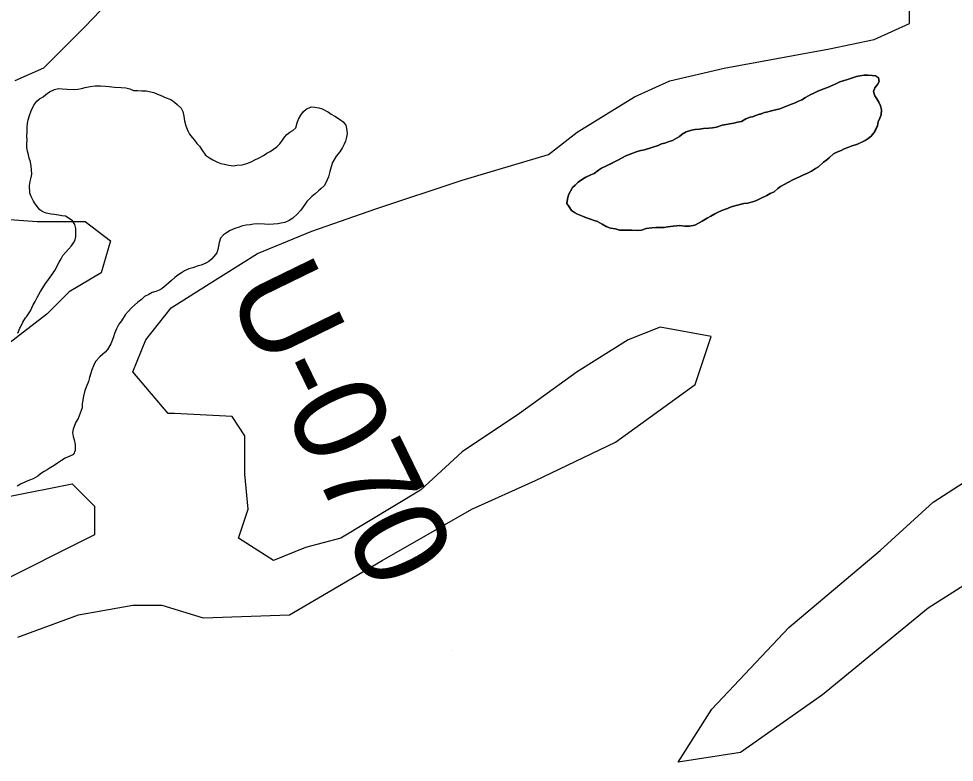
# Model space of a CAD drawing. Extents: x 3177385 to 3215275, y 903885 to 929304.
# Drawn here: x 3187679 to 3188514, y 913275 to 913939 of the extents above; entities that cross this region are included whole.
import ezdxf

# ---------------------------------------------------------------- set-up
doc = ezdxf.new("R2010")
doc.units = 0
for name, color, linetype in [('V-RIVR-RANG', 7, 'Continuous'), ('V-RIVR-RANG-IDEN', 7, 'Continuous'), ('V-SITE-VEGE', 7, 'Continuous'), ('V-TOPO-SHOR', 7, 'Continuous')]:
    doc.layers.add(name, color=color, linetype=linetype)

msp = doc.modelspace()

# ---------------------------------------------------------------- linework, layer by layer
at = {"layer": 'V-RIVR-RANG'}
msp.add_line((3188065.58, 913375.16), (3188065.58, 913375.16), dxfattribs=at)
at = {"layer": 'V-SITE-VEGE'}
for points in [[(3187852.4, 914017.74), (3187792.5, 913989.19), (3187738.3, 913932.1), (3187701.21, 913895), (3187675.54, 913883.58)], [(3187678.39, 913386.92), (3187732.59, 913406.9), (3187781.09, 913415.47), (3187806.76, 913415.47), (3187843.85, 913404.05), (3187920.87, 913406.9), (3188003.59, 913455.43), (3188083.47, 913501.1), (3188140.52, 913526.79), (3188211.84, 913561.04), (3188283.15, 913612.42), (3188297.42, 913655.23), (3188251.77, 913663.8), (3188223.25, 913652.38), (3188177.61, 913623.84), (3188126.26, 913586.73), (3188074.91, 913552.47), (3188037.83, 913518.22), (3187966.51, 913475.41), (3187935.13, 913466.85), (3187906.6, 913455.43), (3187875.23, 913475.41), (3187883.78, 913501.1), (3187880.93, 913532.49), (3187880.93, 913566.75), (3187869.52, 913583.87), (3187818.17, 913586.73), (3187812.47, 913586.73), (3187781.09, 913623.84), (3187792.5, 913652.38), (3187815.32, 913680.92), (3187846.7, 913700.9), (3187892.34, 913729.44), (3187940.84, 913749.42), (3187997.89, 913769.41), (3188074.91, 913795.1), (3188151.93, 913817.93), (3188177.61, 913837.91), (3188228.95, 913869.31), (3188260.33, 913883.58), (3188308.83, 913895), (3188402.97, 913912.12), (3188442.9, 913920.69), (3188474.28, 913934.96), (3188474.28, 913946.38)], [(3188443.32, 913870.14), (3188442.34, 913874.21), (3188443.47, 913877.39), (3188445.67, 913880.32), (3188447.22, 913883.07), (3188446.65, 913886.28), (3188444.13, 913888.04), (3188441.15, 913888.53), (3188437.32, 913888.82), (3188433.91, 913888.68), (3188430.05, 913888.12), (3188427.05, 913887.55), (3188422.55, 913886.15), (3188419.11, 913884.94), (3188415.03, 913883.75), (3188412.03, 913882.75), (3188408.58, 913881.12), (3188405.78, 913879.89), (3188401.04, 913877.86), (3188396.96, 913876.25), (3188391.79, 913874.01), (3188388.99, 913872.79), (3188385.76, 913871.15), (3188381.45, 913868.9), (3188378.21, 913866.83), (3188375.4, 913865.4), (3188372.39, 913863.97), (3188368.95, 913862.77), (3188365.94, 913861.55), (3188361.64, 913859.94), (3188358.63, 913858.72), (3188354.77, 913857.74), (3188351.12, 913856.96), (3188346.84, 913855.78), (3188344.91, 913855.39), (3188343.4, 913854.78), (3188341.47, 913853.97), (3188340.4, 913853.78), (3188336.31, 913852.37), (3188334.16, 913851.56), (3188332.02, 913851.18), (3188328.37, 913849.77), (3188324.26, 913847.3), (3188320.84, 913846.73), (3188317.41, 913845.95), (3188313.99, 913845.38), (3188310.78, 913844.81), (3188307.13, 913844.04), (3188301.98, 913842.44), (3188298.34, 913841.66), (3188295.13, 913841.31), (3188290.43, 913840.98), (3188287.01, 913840.41), (3188282.96, 913840.29), (3188279.74, 913839.5), (3188275.02, 913838.11), (3188271.35, 913836.06), (3188268.96, 913833.98), (3188262.92, 913830.48), (3188259.05, 913829.28), (3188256.04, 913828.07), (3188253.04, 913827.49), (3188250.03, 913826.06), (3188237.78, 913822.06), (3188234.57, 913821.49)], [(3188234.57, 913821.49), (3188231.14, 913820.49), (3188224.9, 913818.07), (3188221.25, 913816.65), (3188217.37, 913814.6), (3188214.56, 913813.17), (3188211.55, 913811.74), (3188203.78, 913807.64), (3188199.27, 913805.82), (3188196.67, 913803.95), (3188192.98, 913801.04), (3188189.97, 913799.83), (3188185.45, 913797.79), (3188182.42, 913795.94), (3188178.52, 913793.04), (3188175.91, 913790.53), (3188173.52, 913788.45), (3188171.74, 913785.08), (3188169.96, 913781.92), (3188169.03, 913778.1), (3188168.52, 913774.06), (3188170.37, 913771.03), (3188172.66, 913768), (3188175.18, 913766.24), (3188177.92, 913764.69), (3188182.36, 913762.89), (3188185.95, 913761.32), (3188189.55, 913760.17), (3188192.94, 913759.04), (3188195.9, 913758.12), (3188200.12, 913755.68), (3188203.7, 913753.47), (3188207.29, 913752.12), (3188211.75, 913751.38), (3188215.36, 913750.46), (3188218.56, 913750.39), (3188231.77, 913750.1), (3188235.19, 913750.46), (3188239.28, 913751.86), (3188244.19, 913752.4), (3188248.04, 913752.74), (3188251.87, 913752.66), (3188255.29, 913752.8), (3188258.71, 913753.16), (3188263.42, 913753.91), (3188269.18, 913754.43), (3188273.65, 913753.9), (3188277.92, 913754.02), (3188282.84, 913754.77), (3188286.51, 913756.83), (3188289.31, 913758.26), (3188293.85, 913760.94), (3188297.09, 913762.79), (3188300.54, 913764.85), (3188304.21, 913766.69), (3188308.3, 913768.52), (3188311.95, 913769.72), (3188315.18, 913771.15), (3188318.4, 913772.15), (3188326.33, 913774.11), (3188330.18, 913774.45), (3188336.4, 913776.24), (3188339.63, 913777.66), (3188342.65, 913779.31), (3188346.96, 913781.35), (3188349.98, 913782.99), (3188353.42, 913784.62), (3188356.9, 913787.53), (3188359.28, 913789.4), (3188362.95, 913791.45), (3188365.76, 913792.89), (3188371.37, 913795.97), (3188376.1, 913798), (3188379.12, 913799.43), (3188383.42, 913801.25), (3188386.87, 913802.89), (3188390.54, 913805.37), (3188393.14, 913807.02), (3188397.49, 913810.98), (3188400.52, 913813.26), (3188402.91, 913815.34), (3188406.39, 913818.47), (3188409.41, 913819.89), (3188413.28, 913821.52), (3188416.08, 913822.95), (3188419.31, 913824.16), (3188422.32, 913825.38), (3188427.9, 913827.18), (3188434.8, 913830.44), (3188437.39, 913832.31), (3188440, 913834.38), (3188442.62, 913837.31), (3188445.95, 913843.64), (3188446.45, 913847.04), (3188447.8, 913850.21), (3188448.93, 913853.17), (3188449.24, 913857.65), (3188448.46, 913861.29), (3188447.04, 913864.52), (3188445.19, 913867.75), (3188443.32, 913870.14)], [(3187658.43, 913760.84), (3187695.51, 913757.99), (3187738.3, 913757.99), (3187761.12, 913740.86), (3187752.56, 913712.32), (3187724.04, 913695.19), (3187704.07, 913675.21), (3187655.57, 913638.11)], [(3188585.72, 913472.92), (3188491.18, 913412.73), (3188396.64, 913335.34), (3188323.59, 913283.74), (3188267.72, 913275.14), (3188297.8, 913322.44), (3188366.56, 913395.53), (3188448.21, 913464.32), (3188495.48, 913507.31), (3188568.53, 913554.61)], [(3187669.84, 913512.51), (3187726.89, 913523.93), (3187746.86, 913503.95), (3187746.86, 913478.26), (3187655.57, 913432.59)]]:
    msp.add_lwpolyline(points, dxfattribs=at)
at = {"layer": 'V-TOPO-SHOR'}
for points in [[(3188250.03, 913826.06), (3188253.04, 913827.49), (3188256.04, 913828.07), (3188259.05, 913829.28), (3188262.92, 913830.48), (3188268.96, 913833.97), (3188271.35, 913836.06), (3188275.02, 913838.11), (3188279.74, 913839.5), (3188282.96, 913840.29), (3188287.01, 913840.41), (3188290.43, 913840.98), (3188295.13, 913841.31), (3188298.34, 913841.66), (3188301.98, 913842.44), (3188307.13, 913844.04), (3188310.78, 913844.81), (3188313.99, 913845.38), (3188317.41, 913845.95), (3188320.84, 913846.73), (3188324.26, 913847.3), (3188328.37, 913849.77), (3188332.02, 913851.18), (3188334.16, 913851.56), (3188336.31, 913852.37), (3188340.4, 913853.78), (3188341.46, 913853.97), (3188343.4, 913854.78), (3188344.91, 913855.39), (3188346.84, 913855.77), (3188351.12, 913856.96), (3188354.77, 913857.74), (3188358.63, 913858.72), (3188361.64, 913859.94), (3188365.94, 913861.55), (3188368.95, 913862.77), (3188372.39, 913863.97), (3188375.4, 913865.4), (3188378.21, 913866.83), (3188381.45, 913868.9), (3188385.76, 913871.15), (3188388.99, 913872.79), (3188391.79, 913874.01), (3188396.96, 913876.25), (3188401.04, 913877.86), (3188405.78, 913879.89), (3188408.58, 913881.12), (3188412.03, 913882.75), (3188415.03, 913883.75), (3188419.11, 913884.94), (3188422.55, 913886.15), (3188427.05, 913887.55), (3188430.05, 913888.12), (3188433.91, 913888.68), (3188437.32, 913888.82), (3188441.15, 913888.53), (3188444.13, 913888.04), (3188444.76, 913887.6), (3188446.65, 913886.28), (3188447.22, 913883.07), (3188445.67, 913880.32), (3188443.47, 913877.39), (3188442.34, 913874.21), (3188443.32, 913870.14), (3188445.19, 913867.75), (3188447.04, 913864.52), (3188448.46, 913861.29), (3188449.24, 913857.65), (3188448.93, 913853.17), (3188447.8, 913850.21), (3188446.45, 913847.04), (3188445.95, 913843.64), (3188444.18, 913840.27), (3188442.62, 913837.31), (3188440, 913834.38), (3188437.39, 913832.31), (3188434.8, 913830.44), (3188431.78, 913829.01), (3188427.9, 913827.18), (3188422.32, 913825.38), (3188419.31, 913824.16), (3188416.08, 913822.95), (3188413.28, 913821.52), (3188409.41, 913819.89), (3188406.39, 913818.47), (3188402.91, 913815.34), (3188400.52, 913813.26), (3188397.49, 913810.98), (3188393.14, 913807.02), (3188390.54, 913805.37), (3188386.87, 913802.89), (3188383.42, 913801.25), (3188379.12, 913799.43), (3188376.1, 913798), (3188371.37, 913795.97), (3188365.76, 913792.89), (3188362.95, 913791.45), (3188359.28, 913789.4), (3188356.9, 913787.53), (3188353.42, 913784.62), (3188349.98, 913782.99)], [(3187693.21, 913774.8), (3187692.37, 913776.09), (3187690.11, 913780.41), (3187688.9, 913783.42), (3187688.83, 913790.24), (3187689.33, 913793.86), (3187690.05, 913797.47), (3187690.75, 913800.44), (3187690.62, 913804.28), (3187690.26, 913807.49), (3187689.49, 913811.34), (3187688.49, 913814.56), (3187687.71, 913817.56), (3187686.93, 913820.99), (3187686.35, 913824.2), (3187686.21, 913827.41), (3187686.49, 913830.81), (3187686.35, 913834.01), (3187686.66, 913838.49), (3187686.74, 913842.32), (3187686.81, 913845.73), (3187687.52, 913848.92), (3187688.67, 913852.73), (3187690.25, 913856.96), (3187692.49, 913861.82), (3187695.33, 913865.38), (3187697.72, 913867.47), (3187700.75, 913869.53), (3187703.14, 913871.4), (3187706.6, 913873.89), (3187710.91, 913875.93), (3187714.56, 913876.7), (3187717.75, 913876.64), (3187722.22, 913876.11), (3187728.19, 913875.99), (3187731.82, 913876.34), (3187735.03, 913876.91), (3187738.46, 913877.69), (3187742.75, 913878.66), (3187747.45, 913879.2), (3187752.14, 913879.1), (3187756.4, 913879.01), (3187759.8, 913878.51), (3187764.48, 913877.99), (3187770.45, 913877.65), (3187774.71, 913877.34), (3187778.31, 913876.41), (3187781.69, 913875.06), (3187785.11, 913874.99), (3187788.94, 913874.69), (3187792.99, 913874.82), (3187799.57, 913873.19), (3187802.95, 913871.84), (3187806.76, 913870.26), (3187809.92, 913868.7), (3187815, 913866.89), (3187818.16, 913864.69), (3187820.67, 913862.5), (3187824.01, 913859.23), (3187825.66, 913856.42), (3187826.63, 913852.14), (3187827.18, 913847.86), (3187828.15, 913843.36), (3187829.98, 913839.06), (3187831.41, 913836.04), (3187833.9, 913833), (3187835.99, 913830.83), (3187838.05, 913827.8), (3187840.34, 913825.19), (3187842.41, 913821.95), (3187845.93, 913817.18), (3187849.3, 913814.98), (3187852.45, 913812.99), (3187856.68, 913810.98), (3187859.64, 913809.85), (3187862.82, 913809.14), (3187866.64, 913808.42), (3187870.68, 913807.91), (3187873.89, 913808.27), (3187878.59, 913808.81), (3187882.67, 913810), (3187886.54, 913811.41), (3187889.77, 913813.05), (3187893.01, 913814.68), (3187897.54, 913817.15), (3187900.56, 913819), (3187903.58, 913820.64), (3187906.61, 913822.71), (3187909.43, 913824.79), (3187912.26, 913827.5), (3187914.67, 913830.64), (3187916.22, 913833.38), (3187918.41, 913835.9), (3187921.01, 913837.76), (3187923.81, 913839.19), (3187926.43, 913841.7), (3187927.8, 913846.15), (3187928.93, 913849.32), (3187930.93, 913852.9), (3187933.35, 913856.26), (3187935.74, 913858.35)], [(3187935.74, 913858.35), (3187940.26, 913860.38), (3187943.45, 913860.31), (3187947.06, 913859.6), (3187950.03, 913858.68), (3187955.73, 913855.79), (3187958.03, 913853.82), (3187961.41, 913852.25), (3187965.61, 913849.39), (3187968.77, 913847.19), (3187971.26, 913844.15), (3187971.62, 913841.16), (3187972.17, 913836.67), (3187971.67, 913833.27), (3187970.96, 913829.87), (3187969.62, 913827.13), (3187968.06, 913824.17), (3187965.85, 913820.38), (3187962.57, 913816.4), (3187959.25, 913810.72), (3187957.88, 913806.91), (3187956.94, 913802.66), (3187955.77, 913797.99), (3187954.44, 913795.25), (3187951.98, 913790.18), (3187949.15, 913787.47), (3187946.76, 913785.39), (3187943.72, 913782.9), (3187940.9, 913780.4), (3187938.5, 913777.89), (3187936.32, 913775.8), (3187934.56, 913773.28), (3187930.83, 913768.24), (3187927.77, 913764.68), (3187923.85, 913761.14), (3187920.61, 913759.08), (3187916.52, 913757.03), (3187913.52, 913756.67), (3187910.52, 913755.88), (3187906.68, 913755.75), (3187902.2, 913755.42), (3187898.36, 913755.71), (3187892.61, 913755.84), (3187888.77, 913755.7), (3187885.77, 913755.13), (3187882.13, 913754.78), (3187878.92, 913754.21), (3187875.91, 913752.99), (3187872.05, 913751.79), (3187867.96, 913749.96), (3187864.5, 913747.9), (3187861.91, 913746.25), (3187859.29, 913743.32), (3187858.13, 913739.3), (3187857.43, 913736.11), (3187856.73, 913733.14), (3187855.8, 913729.96), (3187853.39, 913726.82), (3187851.2, 913724.3), (3187848.82, 913722.43), (3187846.23, 913720.78), (3187841.92, 913719.17), (3187838.49, 913718.17), (3187834.41, 913716.77), (3187830.98, 913715.78), (3187827.1, 913713.94), (3187824.29, 913712.29), (3187821.05, 913710.02), (3187818.45, 913708.15), (3187815.4, 913705.45), (3187813.22, 913703.15), (3187810.62, 913701.07), (3187807.14, 913698.16), (3187804.34, 913696.72), (3187801.54, 913695.51), (3187798.33, 913694.72), (3187795.09, 913692.87), (3187791.42, 913691.03), (3187788.81, 913688.53), (3187785.56, 913686.04), (3187782.52, 913683.33), (3187779.9, 913680.83), (3187776.85, 913677.69), (3187774.23, 913674.76), (3187770.7, 913669.29), (3187768.51, 913666.35), (3187766.28, 913662.14), (3187764.71, 913658.12), (3187763.79, 913655.15), (3187762.44, 913651.77), (3187761.31, 913648.8), (3187758.43, 913643.75), (3187756.24, 913641.24), (3187753.86, 913639.37), (3187751.46, 913637.07), (3187747.75, 913633.1), (3187745.75, 913629.3), (3187744.39, 913625.5), (3187743.48, 913622.53), (3187742.33, 913618.72), (3187741.4, 913615.32)], [(3188349.98, 913782.99), (3188346.96, 913781.35), (3188342.65, 913779.31), (3188339.63, 913777.66), (3188336.4, 913776.24), (3188330.18, 913774.45), (3188326.33, 913774.11), (3188318.4, 913772.15), (3188315.18, 913771.15), (3188311.95, 913769.72), (3188308.3, 913768.52), (3188304.21, 913766.69), (3188300.54, 913764.85), (3188297.09, 913762.79), (3188293.85, 913760.94), (3188289.31, 913758.26), (3188286.51, 913756.83), (3188282.84, 913754.77), (3188277.92, 913754.03), (3188273.65, 913753.9), (3188269.18, 913754.43), (3188263.42, 913753.91), (3188258.71, 913753.16), (3188255.29, 913752.8), (3188251.87, 913752.66), (3188248.04, 913752.74), (3188244.19, 913752.4), (3188239.28, 913751.86), (3188235.19, 913750.46), (3188231.77, 913750.1), (3188226.44, 913750.22), (3188221.97, 913750.31), (3188218.56, 913750.39), (3188215.36, 913750.46), (3188211.75, 913751.38), (3188207.29, 913752.12), (3188203.7, 913753.47), (3188200.12, 913755.68), (3188195.9, 913758.12), (3188192.94, 913759.04), (3188189.55, 913760.17), (3188185.95, 913761.32), (3188182.36, 913762.89), (3188177.92, 913764.69), (3188175.18, 913766.24), (3188172.66, 913768), (3188170.37, 913771.03), (3188168.52, 913774.06), (3188169.03, 913778.1), (3188169.97, 913781.92), (3188171.74, 913785.08), (3188173.52, 913788.45), (3188175.91, 913790.53), (3188178.52, 913793.04), (3188182.42, 913795.94), (3188185.45, 913797.79), (3188189.97, 913799.83), (3188192.98, 913801.04), (3188196.67, 913803.95), (3188199.27, 913805.82), (3188203.78, 913807.64), (3188207.66, 913809.69), (3188211.55, 913811.74), (3188214.56, 913813.17), (3188217.37, 913814.6), (3188221.25, 913816.65), (3188224.9, 913818.07), (3188231.14, 913820.49), (3188234.57, 913821.49), (3188237.78, 913822.06), (3188250.03, 913826.06)], [(3187730.09, 913744.8), (3187729.95, 913748.64), (3187730.02, 913751.84), (3187729.03, 913755.48), (3187727.18, 913758.72), (3187724.03, 913760.71), (3187720.88, 913762.9), (3187717.47, 913763.19), (3187714.49, 913763.68), (3187710.88, 913764.18), (3187707.91, 913764.67), (3187703.66, 913765.62), (3187700.48, 913766.75), (3187697.96, 913768.51), (3187695.46, 913771.34), (3187693.21, 913774.8)], [(3187678.13, 913658.25), (3187680.15, 913662.9), (3187680.8, 913663.74), (3187682.82, 913668.18), (3187685.24, 913671.96), (3187685.91, 913673.02), (3187687.88, 913675.75), (3187689.64, 913678.27), (3187692.11, 913683.76), (3187693.87, 913686.71), (3187695.66, 913690.3), (3187698.54, 913695.56), (3187700.53, 913698.94), (3187702.96, 913702.72), (3187704.94, 913705.45), (3187707.79, 913709.23), (3187708.01, 913709.65), (3187709.55, 913711.75), (3187710.43, 913713.01), (3187711.53, 913714.7), (3187713.76, 913719.13), (3187715.1, 913721.87), (3187716.87, 913724.82), (3187718.42, 913727.77), (3187721.04, 913730.7), (3187723.44, 913733.21), (3187726.07, 913736.35), (3187727.83, 913738.87), (3187729.38, 913741.82), (3187730.09, 913744.8)], [(3187741.4, 913615.32), (3187739.38, 913610.25), (3187738.03, 913607.08), (3187736.85, 913601.99), (3187736.36, 913598.8), (3187735.85, 913594.97), (3187735.78, 913591.56), (3187732.16, 913582.04)], [(3187732.16, 913582.04), (3187730.18, 913578.88), (3187728.84, 913575.92), (3187727.7, 913572.75), (3187727, 913569.78), (3187727.77, 913566.14), (3187728.56, 913563.13), (3187729.33, 913558.85), (3187729.42, 913553.52), (3187727.86, 913550.14), (3187724.63, 913548.5), (3187720.54, 913546.67), (3187717.29, 913544.61), (3187713.61, 913542.13), (3187710.58, 913540.06), (3187707.13, 913538.21), (3187704.32, 913536.36), (3187701.73, 913534.7), (3187698.48, 913532.64), (3187696.1, 913530.77), (3187691.99, 913528.3), (3187688.56, 913527.09), (3187685.11, 913525.67), (3187680.8, 913523.42), (3187677.57, 913521.78)]]:
    msp.add_lwpolyline(points, dxfattribs=at)

# ---------------------------------------------------------------- texts
at = {"layer": 'V-RIVR-RANG-IDEN'}
msp.add_text('U-070', height=83, rotation=295.98933, dxfattribs=at).set_placement((3187863.86, 913696.5))

doc.saveas('drawing.dxf')
